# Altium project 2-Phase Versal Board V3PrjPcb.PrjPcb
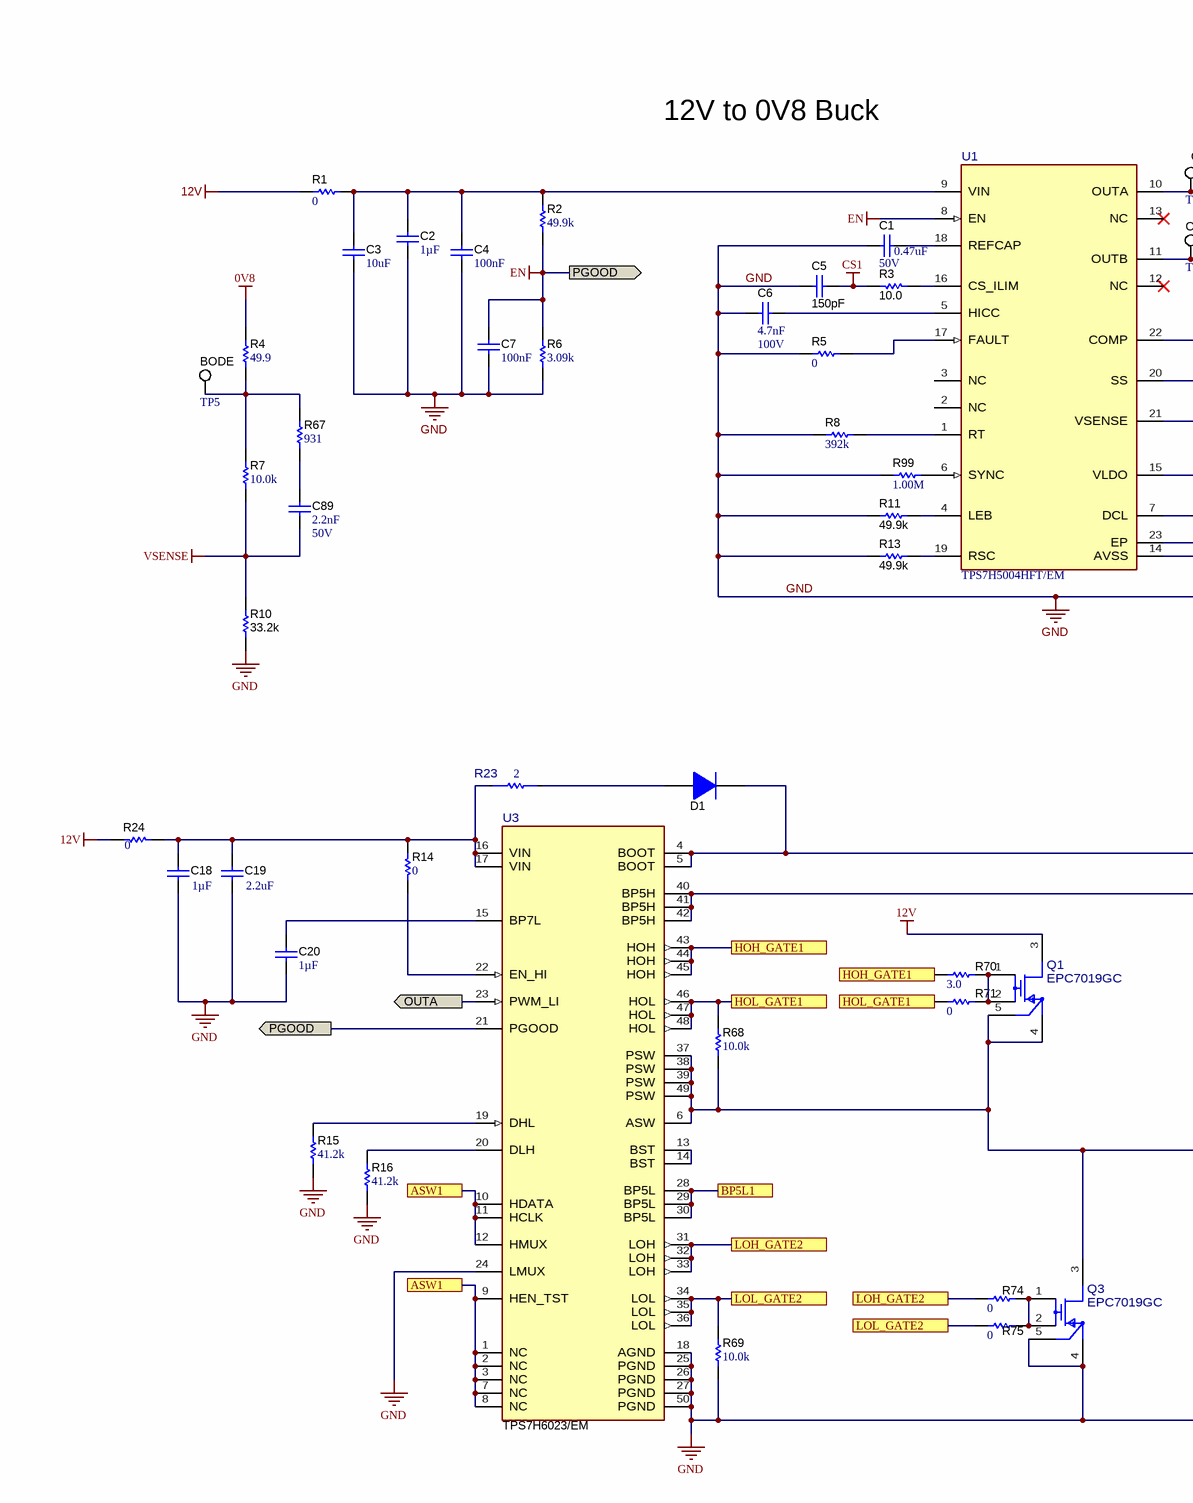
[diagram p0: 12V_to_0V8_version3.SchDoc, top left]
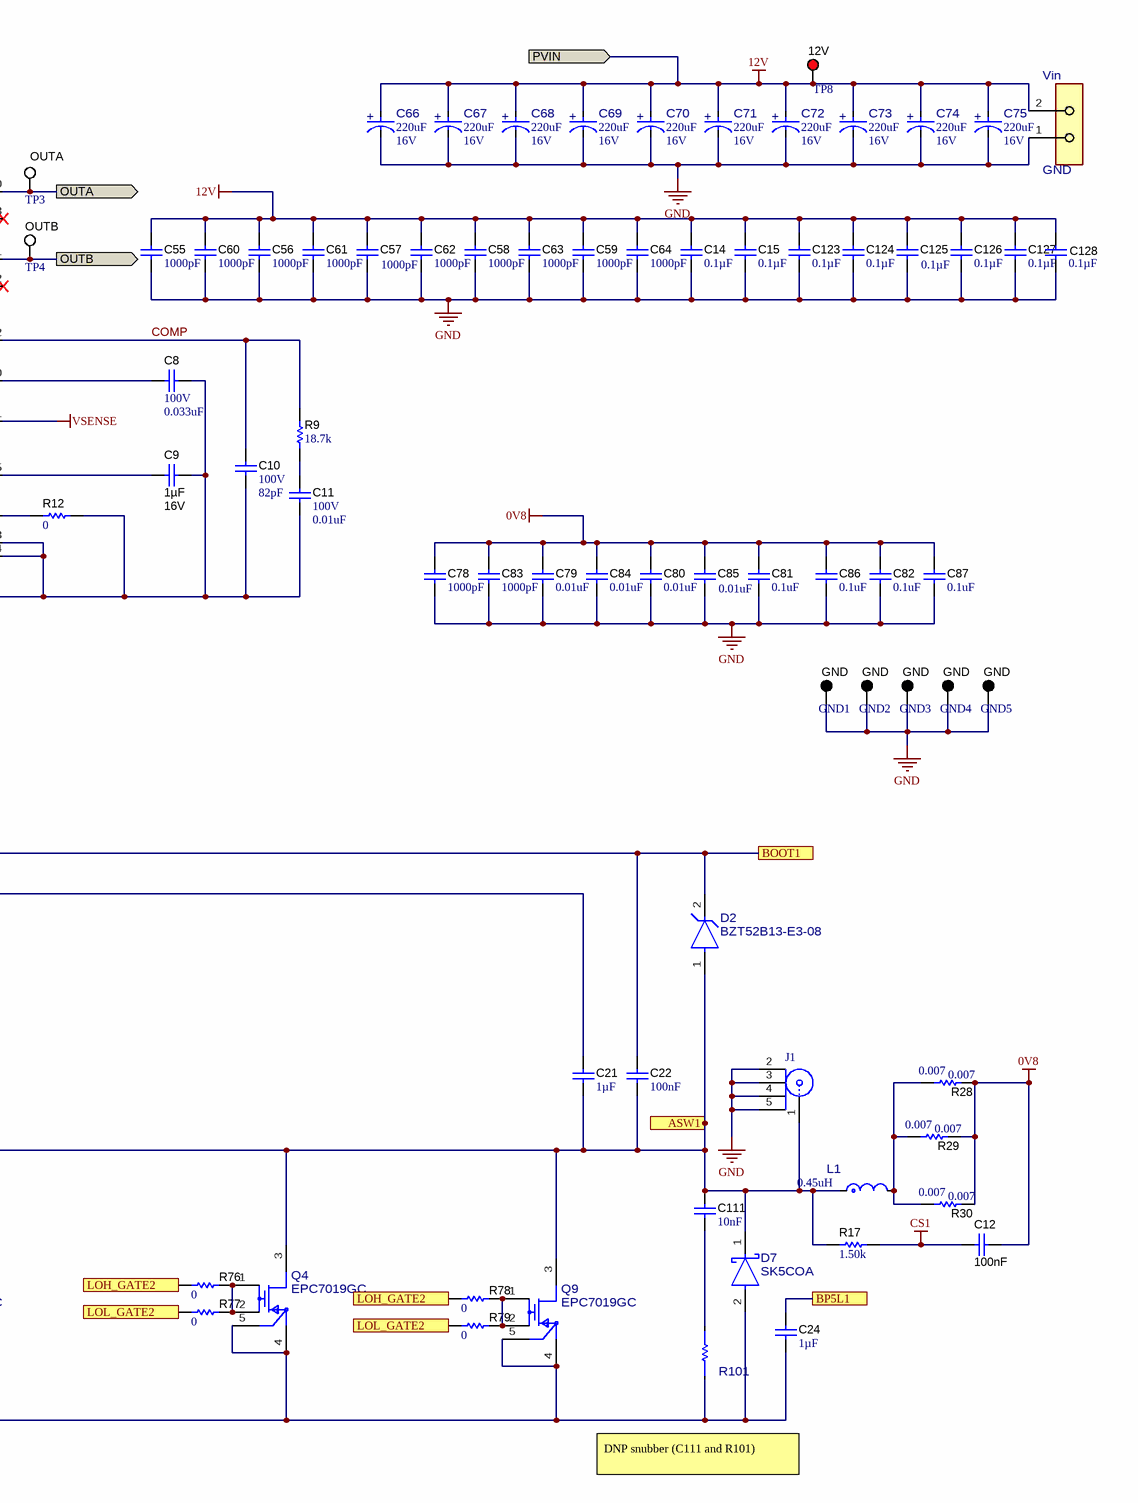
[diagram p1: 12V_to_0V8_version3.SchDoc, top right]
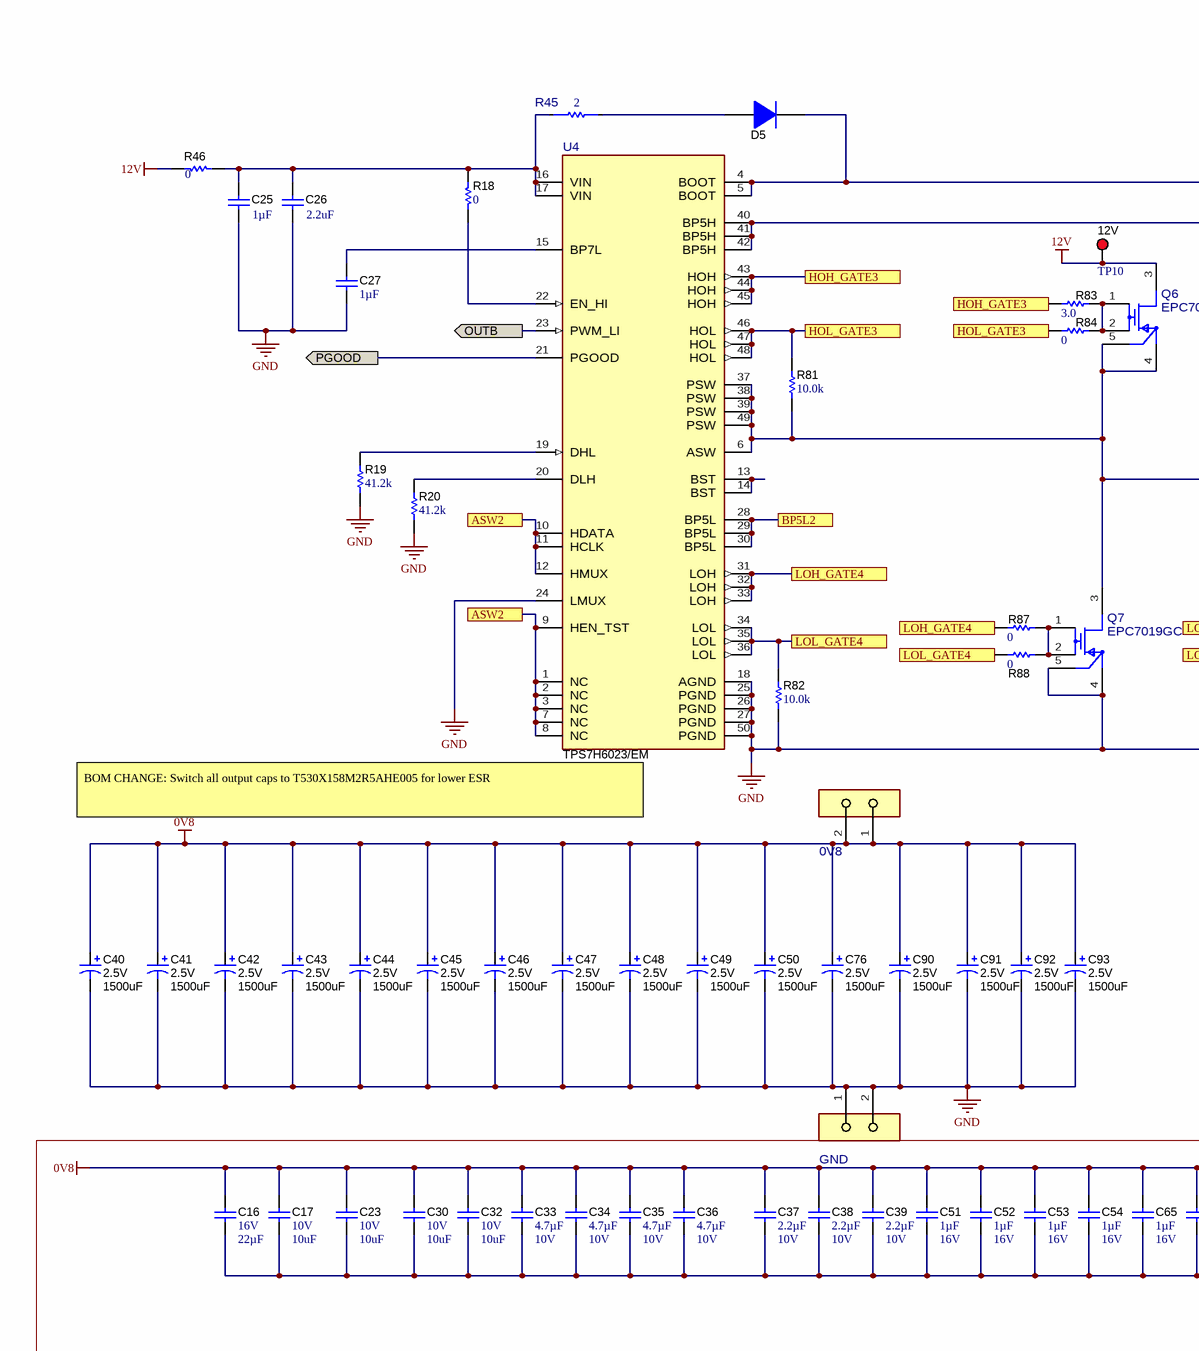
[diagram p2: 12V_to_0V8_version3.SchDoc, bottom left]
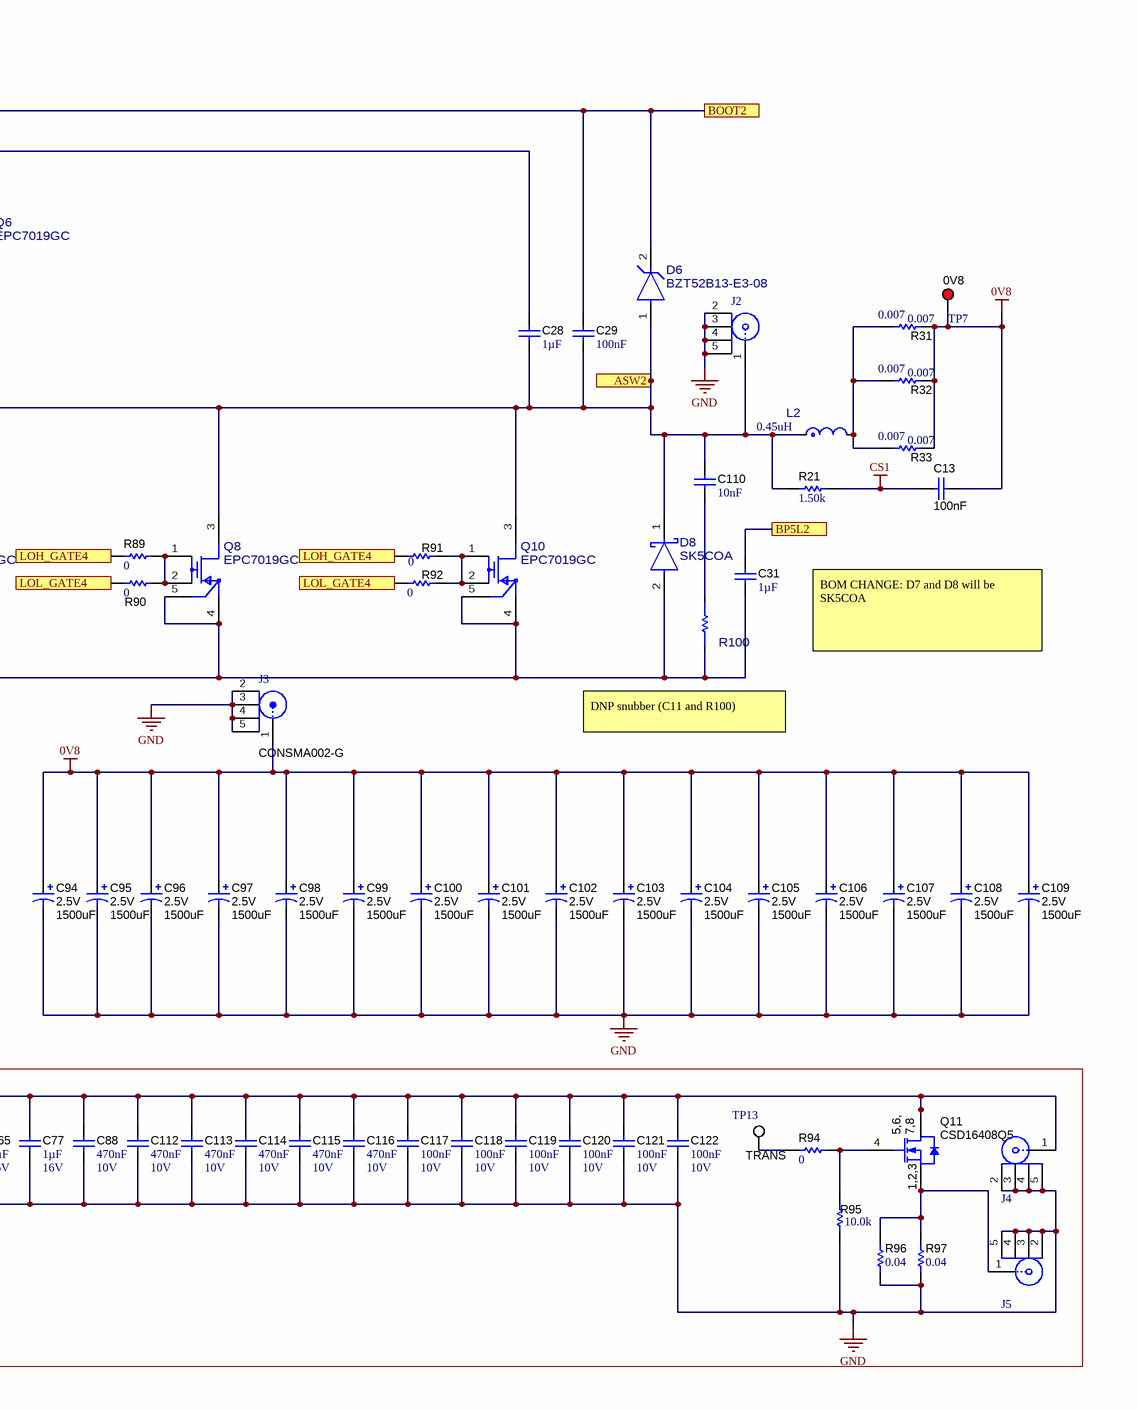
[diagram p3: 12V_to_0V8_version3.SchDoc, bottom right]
CopyrightYear: 2018; PCB_Layout: Who did the Layout?; PCB_Rev: E1; PRJ_Customer: Public Release; PRJ_Engineer: Enter name of project lead; PRJ_Number: XXX###; PRJ_Title: Change in menu Project|Project Options|Parameters; SCH_Rev: E1; TechSupport: http://www.ti.com/support; TID: N/A
2 sheets, 244 parts. Net scope: flat (ports and power ports of the same name join across sheets).
Board file: Versal_V3.PcbDoc
Sheets:
  12V_to_0V8_version3.SchDoc
  Hardware.SchDoc

## Sheet 12V_to_0V8_version3.SchDoc
size 431 x 558 mm; Date: Not shown in title block; ApprovedBy: Not shown in title block; CheckedBy: Not shown in title block; Author: Not shown in title block; CompanyName: Not shown in title block; Engineer: Not shown in title block; Organization: Not shown in title block; Address1: Not shown in title block; Address2: Not shown in title block; Address3: Not shown in title block; Address4: Not shown in title block; DocumentNumber: 1; Revision: Use project parameter SCH_Rev; SheetNumber: 1; SheetTotal: 2; PageSetup: Record=PageOptions¦CenterHorizontal=True¦CenterVertical=True¦PrintScale=1.00¦XCorrection=1.00¦YCorrection=1.00¦PrintKind=0¦BorderSize=5000000¦LeftOffset=0¦BottomOffset=0¦Orientation=2¦PaperLength=1000¦PaperWidth=1000¦Scale=100¦PaperSource=15¦PrintQuality=600¦MediaType=1¦DitherType=10¦PaperKind=Letter¦PrintScaleMode=1

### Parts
0V8  1929517  [FP-1929517_HDR2-MFG]  (value not drawn)
C1  VDC_V: 50V  ValueDisplayed: 0.47uF  [0805L]  (hidden comment: C2012X5R1H474K125AB)
C2  Cap_F: 1µF  [0603L]  (hidden comment: CGA3E1X7R1C105K080AC)
C3  ValueDisplayed: 10uF  [1210_270L]  (hidden comment: GRM32ER71H106KA12L)
C4  Cap_F: 100nF  [0603L]  (hidden comment: C0603C104K5RACAUTO)
C5  Cap_F: 150pF  [0603L]  (hidden comment: 06033C101KAT2A)
C6  Cap_F: 4.7nF  VDC_V: 100V  [0603L]  (hidden comment: GCM188R72A472KA37D)
C7  Cap_F: 100nF  [0603L]  (hidden comment: C0603C104K5RACAUTO)
C8  VDC_V: 100V  ValueDisplayed: 0.033uF  [0603L]  (hidden comment: CGA3E3X7S2A333K080AB)
C9  Cap_F: 1µF  VDC_V: 16V  [0603L]  (hidden comment: CGA3E1X7R1C105K080AC)
C10  VDC_V: 100V  ValueDisplayed: 82pF  [0603]  (hidden comment: GRM1885C2A820JA01D)
C11  VDC_V: 100V  ValueDisplayed: 0.01uF  [0603]  (hidden comment: CGA3E2X7R2A103K080AA)
C12  Cap_F: 100nF  [0603L]  (hidden comment: 06035C104KAZ2A)
C13  Cap_F: 100nF  [0603L]  (hidden comment: 06035C104KAZ2A)
C14  ValueDisplayed: 0.1µF  [0603]  (hidden comment: GCM188R71E104KA57D)
C15  ValueDisplayed: 0.1µF  [0603]  (hidden comment: GCM188R71E104KA57D)
C16  VDC_V: 16V  ValueDisplayed: 22µF  [1210_270]  (hidden comment: CL32B226KOJNFNE)
C17  VDC_V: 10V  ValueDisplayed: 10uF  [1206]  (hidden comment: C3216X7R1A106K085AC)
C18  ValueDisplayed: 1µF  [0805L]  (hidden comment: 08055C105K4Z2A)
C19  ValueDisplayed: 2.2uF  [0805L]  (hidden comment: CGA4J3X7R1H225K125AB)
C20  Cap_F: 1µF  [0805_HV]  (hidden comment: 08055C105K4Z2A)
C21  Cap_F: 1µF  [0805L]  (hidden comment: 08055C105K4Z2A)
C22  Cap_F: 100nF  [0603L]  (hidden comment: C0603C104K5RACAUTO)
C23  VDC_V: 10V  ValueDisplayed: 10uF  [1206]  (hidden comment: C3216X7R1A106K085AC)
C24  Cap_F: 1µF  [0805L]  (hidden comment: 08055C105K4Z2A)
C25  ValueDisplayed: 1µF  [0805L]  (hidden comment: 08055C105K4Z2A)
C26  ValueDisplayed: 2.2uF  [0805L]  (hidden comment: CGA4J3X7R1H225K125AB)
C27  Cap_F: 1µF  [0805_HV]  (hidden comment: 08055C105K4Z2A)
C28  Cap_F: 1µF  [0805L]  (hidden comment: 08055C105K4Z2A)
C29  Cap_F: 100nF  [0603L]  (hidden comment: C0603C104K5RACAUTO)
C30  VDC_V: 10V  ValueDisplayed: 10uF  [1206]  (hidden comment: C3216X7R1A106K085AC)
C31  Cap_F: 1µF  [0805L]  (hidden comment: 08055C105K4Z2A)
C32  VDC_V: 10V  ValueDisplayed: 10uF  [1206]  (hidden comment: C3216X7R1A106K085AC)
C33  Cap_F: 4.7µF  VDC_V: 10V  [0805_HV]  (hidden comment: 885012207025)
C34  Cap_F: 4.7µF  VDC_V: 10V  [0805_HV]  (hidden comment: 885012207025)
C35  Cap_F: 4.7µF  VDC_V: 10V  [0805_HV]  (hidden comment: 885012207025)
C36  Cap_F: 4.7µF  VDC_V: 10V  [0805_HV]  (hidden comment: 885012207025)
C37  Cap_F: 2.2µF  VDC_V: 10V  [0805_HV]  (hidden comment: GRM21BR71A225KA01L)
C38  Cap_F: 2.2µF  VDC_V: 10V  [0805_HV]  (hidden comment: GRM21BR71A225KA01L)
C39  Cap_F: 2.2µF  VDC_V: 10V  [0805_HV]  (hidden comment: GRM21BR71A225KA01L)
C40  VDC_V: 2.5V  ValueDisplayed: 1500uF  [7343-40]  (hidden comment: 2R5TPE1500MF)
C41  VDC_V: 2.5V  ValueDisplayed: 1500uF  [7343-40]  (hidden comment: 2R5TPE1500MF)
C42  VDC_V: 2.5V  ValueDisplayed: 1500uF  [7343-40]  (hidden comment: 2R5TPE1500MF)
C43  VDC_V: 2.5V  ValueDisplayed: 1500uF  [7343-40]  (hidden comment: 2R5TPE1500MF)
C44  VDC_V: 2.5V  ValueDisplayed: 1500uF  [7343-40]  (hidden comment: 2R5TPE1500MF)
C45  VDC_V: 2.5V  ValueDisplayed: 1500uF  [7343-40]  (hidden comment: 2R5TPE1500MF)
C46  VDC_V: 2.5V  ValueDisplayed: 1500uF  [7343-40]  (hidden comment: 2R5TPE1500MF)
C47  VDC_V: 2.5V  ValueDisplayed: 1500uF  [7343-40]  (hidden comment: 2R5TPE1500MF)
C48  VDC_V: 2.5V  ValueDisplayed: 1500uF  [7343-40]  (hidden comment: 2R5TPE1500MF)
C49  VDC_V: 2.5V  ValueDisplayed: 1500uF  [7343-40]  (hidden comment: 2R5TPE1500MF)
C50  VDC_V: 2.5V  ValueDisplayed: 1500uF  [7343-40]  (hidden comment: 2R5TPE1500MF)
C51  Cap_F: 1µF  VDC_V: 16V  [0805_HV]  (hidden comment: C0805C105K4RACAUTO)
C52  Cap_F: 1µF  VDC_V: 16V  [0805_HV]  (hidden comment: C0805C105K4RACAUTO)
C53  Cap_F: 1µF  VDC_V: 16V  [0805_HV]  (hidden comment: C0805C105K4RACAUTO)
C54  Cap_F: 1µF  VDC_V: 16V  [0805_HV]  (hidden comment: C0805C105K4RACAUTO)
C55  ValueDisplayed: 1000pF  [0603]  (hidden comment: 06031C102KAT2A)
C56  ValueDisplayed: 1000pF  [1206]  (hidden comment: 12061C102KAT2A)
C57  ValueDisplayed: 1000pF  [0603]  (hidden comment: 06031C102KAT2A)
C58  ValueDisplayed: 1000pF  [0603]  (hidden comment: 06031C102KAT2A)
C59  ValueDisplayed: 1000pF  [1206]  (hidden comment: 12061C102KAT2A)
C60  ValueDisplayed: 1000pF  [1206]  (hidden comment: 12061C102KAT2A)
C61  ValueDisplayed: 1000pF  [0603]  (hidden comment: 06031C102KAT2A)
C62  ValueDisplayed: 1000pF  [0603]  (hidden comment: 06031C102KAT2A)
C63  ValueDisplayed: 1000pF  [0603]  (hidden comment: 06031C102KAT2A)
C64  ValueDisplayed: 1000pF  [1206]  (hidden comment: 12061C102KAT2A)
C65  Cap_F: 1µF  VDC_V: 16V  [0805_HV]  (hidden comment: C0805C105K4RACAUTO)
C66  ValueDisplayed: 220uF  VDC_V: 16V  [FP-T541X227M016AH6710_2917-MFG]  (hidden comment: T541X227M016AH6710)
C67  ValueDisplayed: 220uF  VDC_V: 16V  [FP-T541X227M016AH6710_2917-MFG]  (hidden comment: T541X227M016AH6710)
C68  ValueDisplayed: 220uF  VDC_V: 16V  [FP-T541X227M016AH6710_2917-MFG]  (hidden comment: T541X227M016AH6710)
C69  ValueDisplayed: 220uF  VDC_V: 16V  [FP-T541X227M016AH6710_2917-MFG]  (hidden comment: T541X227M016AH6710)
C70  ValueDisplayed: 220uF  VDC_V: 16V  [FP-T541X227M016AH6710_2917-MFG]  (hidden comment: T541X227M016AH6710)
C71  ValueDisplayed: 220uF  VDC_V: 16V  [FP-T541X227M016AH6710_2917-MFG]  (hidden comment: T541X227M016AH6710)
C72  ValueDisplayed: 220uF  VDC_V: 16V  [FP-T541X227M016AH6710_2917-MFG]  (hidden comment: T541X227M016AH6710)
C73  ValueDisplayed: 220uF  VDC_V: 16V  [FP-T541X227M016AH6710_2917-MFG]  (hidden comment: T541X227M016AH6710)
C74  ValueDisplayed: 220uF  VDC_V: 16V  [FP-T541X227M016AH6710_2917-MFG]  (hidden comment: T541X227M016AH6710)
C75  ValueDisplayed: 220uF  VDC_V: 16V  [FP-T541X227M016AH6710_2917-MFG]  (hidden comment: T541X227M016AH6710)
C76  VDC_V: 2.5V  ValueDisplayed: 1500uF  [7343-40]  (hidden comment: 2R5TPE1500MF)
C77  Cap_F: 1µF  VDC_V: 16V  [0805_HV]  (hidden comment: C0805C105K4RACAUTO)
C78  ValueDisplayed: 1000pF  [1206L]  (hidden comment: 12061C102KAT2A)
C79  ValueDisplayed: 0.01uF  [1206L]  (hidden comment: C1206C103KARACTU)
C80  ValueDisplayed: 0.01uF  [1206L]  (hidden comment: C1206C103KARACTU)
C81  ValueDisplayed: 0.1uF  [1206_180]  (hidden comment: GRM31CR72E104KW03L)
C82  ValueDisplayed: 0.1uF  [1206_180]  (hidden comment: GRM31CR72E104KW03L)
C83  ValueDisplayed: 1000pF  [1206L]  (hidden comment: 12061C102KAT2A)
C84  ValueDisplayed: 0.01uF  [1206L]  (hidden comment: C1206C103KARACTU)
C85  ValueDisplayed: 0.01uF  [1206L]  (hidden comment: C1206C103KARACTU)
C86  ValueDisplayed: 0.1uF  [1206_180]  (hidden comment: GRM31CR72E104KW03L)
C87  ValueDisplayed: 0.1uF  [1206_180]  (hidden comment: GRM31CR72E104KW03L)
C88  Cap_F: 470nF  VDC_V: 10V  [0603]  (hidden comment: C0603C474K8RACTU)
C89  Cap_F: 2.2nF  VDC_V: 50V  [0805_HV]  (hidden comment: 08055A222JAT2A)
C90  VDC_V: 2.5V  ValueDisplayed: 1500uF  [7343-40]  (hidden comment: 2R5TPE1500MF)
C91  VDC_V: 2.5V  ValueDisplayed: 1500uF  [7343-40]  (hidden comment: 2R5TPE1500MF)
C92  VDC_V: 2.5V  ValueDisplayed: 1500uF  [7343-40]  (hidden comment: 2R5TPE1500MF)
C93  VDC_V: 2.5V  ValueDisplayed: 1500uF  [7343-40]  (hidden comment: 2R5TPE1500MF)
C94  VDC_V: 2.5V  ValueDisplayed: 1500uF  [7343-40]  (hidden comment: 2R5TPE1500MF)
C95  VDC_V: 2.5V  ValueDisplayed: 1500uF  [7343-40]  (hidden comment: 2R5TPE1500MF)
C96  VDC_V: 2.5V  ValueDisplayed: 1500uF  [7343-40]  (hidden comment: 2R5TPE1500MF)
C97  VDC_V: 2.5V  ValueDisplayed: 1500uF  [7343-40]  (hidden comment: 2R5TPE1500MF)
C98  VDC_V: 2.5V  ValueDisplayed: 1500uF  [7343-40]  (hidden comment: 2R5TPE1500MF)
C99  VDC_V: 2.5V  ValueDisplayed: 1500uF  [7343-40]  (hidden comment: 2R5TPE1500MF)
C100  VDC_V: 2.5V  ValueDisplayed: 1500uF  [7343-40]  (hidden comment: 2R5TPE1500MF)
C101  VDC_V: 2.5V  ValueDisplayed: 1500uF  [7343-40]  (hidden comment: 2R5TPE1500MF)
C102  VDC_V: 2.5V  ValueDisplayed: 1500uF  [7343-40]  (hidden comment: 2R5TPE1500MF)
C103  VDC_V: 2.5V  ValueDisplayed: 1500uF  [7343-40]  (hidden comment: 2R5TPE1500MF)
C104  VDC_V: 2.5V  ValueDisplayed: 1500uF  [7343-40]  (hidden comment: 2R5TPE1500MF)
C105  VDC_V: 2.5V  ValueDisplayed: 1500uF  [7343-40]  (hidden comment: 2R5TPE1500MF)
C106  VDC_V: 2.5V  ValueDisplayed: 1500uF  [7343-40]  (hidden comment: 2R5TPE1500MF)
C107  VDC_V: 2.5V  ValueDisplayed: 1500uF  [7343-40]  (hidden comment: 2R5TPE1500MF)
C108  VDC_V: 2.5V  ValueDisplayed: 1500uF  [7343-40]  (hidden comment: 2R5TPE1500MF)
C109  VDC_V: 2.5V  ValueDisplayed: 1500uF  [7343-40]  (hidden comment: 2R5TPE1500MF)
C110  Cap_F: 10nF  [0603]  (hidden comment: 0603ZC103KAT2A)
C111  Cap_F: 10nF  [0603]  (hidden comment: 0603ZC103KAT2A)
C112  Cap_F: 470nF  VDC_V: 10V  [0603]  (hidden comment: C0603C474K8RACTU)
C113  Cap_F: 470nF  VDC_V: 10V  [0603]  (hidden comment: C0603C474K8RACTU)
C114  Cap_F: 470nF  VDC_V: 10V  [0603]  (hidden comment: C0603C474K8RACTU)
C115  Cap_F: 470nF  VDC_V: 10V  [0603]  (hidden comment: C0603C474K8RACTU)
C116  Cap_F: 470nF  VDC_V: 10V  [0603]  (hidden comment: C0603C474K8RACTU)
C117  Cap_F: 100nF  VDC_V: 10V  [0603]  (hidden comment: 885012206020)
C118  Cap_F: 100nF  VDC_V: 10V  [0603]  (hidden comment: 885012206020)
C119  Cap_F: 100nF  VDC_V: 10V  [0603]  (hidden comment: 885012206020)
C120  Cap_F: 100nF  VDC_V: 10V  [0603]  (hidden comment: 885012206020)
C121  Cap_F: 100nF  VDC_V: 10V  [0603]  (hidden comment: 885012206020)
C122  Cap_F: 100nF  VDC_V: 10V  [0603]  (hidden comment: 885012206020)
C123  ValueDisplayed: 0.1µF  [0603]  (hidden comment: GCM188R71E104KA57D)
C124  ValueDisplayed: 0.1µF  [0603]  (hidden comment: GCM188R71E104KA57D)
C125  ValueDisplayed: 0.1µF  [0603]  (hidden comment: GCM188R71E104KA57D)
C126  ValueDisplayed: 0.1µF  [0603]  (hidden comment: GCM188R71E104KA57D)
C127  ValueDisplayed: 0.1µF  [0603]  (hidden comment: GCM188R71E104KA57D)
C128  ValueDisplayed: 0.1µF  [0603]  (hidden comment: GCM188R71E104KA57D)
D1  ES3AB-13-F  [SMB]  (value not drawn)
D2  BZT52B13-E3-08  [FP-BZT52B13-E3-08_SOD123-MFG]
D5  ES3AB-13-F  [SMB]  (value not drawn)
D6  BZT52B13-E3-08  [FP-BZT52B13-E3-08_SOD123-MFG]
D7  SK5COA  [FP-NRVBA340T3G_SMA-MFG]
D8  SK5COA  [FP-NRVBA340T3G_SMA-MFG]
GND  1929517  [FP-1929517_HDR2-MFG]  (value not drawn)
GND1  GND  [Keystone5001]
GND2  GND  [Keystone5001]
GND3  GND  [Keystone5001]
GND4  GND  [Keystone5001]
GND5  GND  [Keystone5001]
J1  SW  [Tek_131-5031-00]  (value not drawn)
J2  SW  [Tek_131-5031-00]  (value not drawn)
J3  CONSMA002-G  [Linx_CONSMA002-G]
J4  SW  [Tek_131-5031-00]  (value not drawn)
J5  SW  [Tek_131-5031-00]  (value not drawn)
L1  value 0.45uH  [FP-XAL1010-451MEB_SMD2-MFG]  (hidden comment: XAL1010-451MEB)
L2  value 0.45uH  [FP-XAL1010-451MEB_SMD2-MFG]  (hidden comment: XAL1010-451MEB)
Q1  EPC7019GC  [FP-EPC7019GC_FSMD-G-MFG]
Q3  EPC7019GC  [FP-EPC7019GC_FSMD-G-MFG]
Q4  EPC7019GC  [FP-EPC7019GC_FSMD-G-MFG]
Q6  EPC7019GC  [FP-EPC7019GC_FSMD-G-MFG]
Q7  EPC7019GC  [FP-EPC7019GC_FSMD-G-MFG]
Q8  EPC7019GC  [FP-EPC7019GC_FSMD-G-MFG]
Q9  EPC7019GC  [FP-EPC7019GC_FSMD-G-MFG]
Q10  EPC7019GC  [FP-EPC7019GC_FSMD-G-MFG]
Q11  CSD16408Q5  [DQH0008A]
R1  ValueDisplayed: 0  [0603L]  (hidden comment: RMCF0603ZT0R00)
R2  ValueDisplayed: 49.9k  [0603L]  (hidden comment: RC0603FR-0749K9L)
R3  ValueDisplayed: 10.0  [0603L]  (hidden comment: RC0603FR-0710RL)
R4  ValueDisplayed: 49.9  [0603L]  (hidden comment: RC0603FR-0749R9L)
R5  ValueDisplayed: 0  [0603L]  (hidden comment: RMCF0603ZT0R00)
R6  ValueDisplayed: 3.09k  [0603L]  (hidden comment: RC0603FR-073K09L)
R7  ValueDisplayed: 10.0k  [0603L]  (hidden comment: RG1608P-103-B-T5)
R8  ValueDisplayed: 392k  [0603L]  (hidden comment: RC0603FR-07392KL)
R9  ValueDisplayed: 18.7k  [0603]  (hidden comment: CRCW060318K7FKEA)
R10  ValueDisplayed: 33.2k  [0603L]  (hidden comment: RG1608P-3322-B-T5)
R11  ValueDisplayed: 49.9k  [0603L]  (hidden comment: RT0603DRE0749K9L)
R12  ValueDisplayed: 0  [0603L]  (hidden comment: RMCF0603ZT0R00)
R13  ValueDisplayed: 49.9k  [0603L]  (hidden comment: RT0603DRE0749K9L)
R14  ValueDisplayed: 0  [0603L]  (hidden comment: RMCF0603ZT0R00)
R15  ValueDisplayed: 41.2k  [0805L]  (hidden comment: RT0805BRD0741K2L)
R16  ValueDisplayed: 41.2k  [0805L]  (hidden comment: RT0805BRD0741K2L)
R17  ValueDisplayed: 1.50k  [0603]  (hidden comment: RT0603BRD071K5L)
R18  ValueDisplayed: 0  [0603L]  (hidden comment: RMCF0603ZT0R00)
R19  ValueDisplayed: 41.2k  [0805L]  (hidden comment: RT0805BRD0741K2L)
R20  ValueDisplayed: 41.2k  [0805L]  (hidden comment: RT0805BRD0741K2L)
R21  ValueDisplayed: 1.50k  [0603]  (hidden comment: RT0603BRD071K5L)
R23  value 2  [FP-RCS06032R00FKEA_0603-MFG]  (hidden comment: RCS06032R00FKEA)
R24  ValueDisplayed: 0  [0603L]  (hidden comment: RMCF0603ZT0R00)
R28  value 0.007  [2512_WIDE]  (hidden comment: KRL6432E-M-R007-F-T1)
R29  value 0.007  [2512_WIDE]  (hidden comment: KRL6432E-M-R007-F-T1)
R30  value 0.007  [2512_WIDE]  (hidden comment: KRL6432E-M-R007-F-T1)
R31  value 0.007  [2512_WIDE]  (hidden comment: KRL6432E-M-R007-F-T1)
R32  value 0.007  [2512_WIDE]  (hidden comment: KRL6432E-M-R007-F-T1)
R33  value 0.007  [2512_WIDE]  (hidden comment: KRL6432E-M-R007-F-T1)
R45  value 2  [FP-RCS06032R00FKEA_0603-MFG]  (hidden comment: RCS06032R00FKEA)
R46  ValueDisplayed: 0  [0603L]  (hidden comment: RMCF0603ZT0R00)
R67  ValueDisplayed: 931  [0603]  (hidden comment: RT0603BRD07931RL)
R68  ValueDisplayed: 10.0k  [0603L]  (hidden comment: RCG060310K0FKEA)
R69  ValueDisplayed: 10.0k  [0603L]  (hidden comment: RCG060310K0FKEA)
R70  ValueDisplayed: 3.0  [0603]  (hidden comment: CRCW06033R00JNEA)
R71  ValueDisplayed: 0  [0603L]  (hidden comment: RMCF0603ZT0R00)
R74  ValueDisplayed: 0  [0603L]  (hidden comment: RMCF0603ZT0R00)
R75  ValueDisplayed: 0  [0603L]  (hidden comment: RMCF0603ZT0R00)
R76  ValueDisplayed: 0  [0603L]  (hidden comment: RMCF0603ZT0R00)
R77  ValueDisplayed: 0  [0603L]  (hidden comment: RMCF0603ZT0R00)
R78  ValueDisplayed: 0  [0603L]  (hidden comment: RMCF0603ZT0R00)
R79  ValueDisplayed: 0  [0603L]  (hidden comment: RMCF0603ZT0R00)
R81  ValueDisplayed: 10.0k  [0603L]  (hidden comment: RCG060310K0FKEA)
R82  ValueDisplayed: 10.0k  [0603L]  (hidden comment: RCG060310K0FKEA)
R83  ValueDisplayed: 3.0  [0603]  (hidden comment: CRCW06033R00JNEA)
R84  ValueDisplayed: 0  [0603L]  (hidden comment: RMCF0603ZT0R00)
R87  ValueDisplayed: 0  [0603L]  (hidden comment: RMCF0603ZT0R00)
R88  ValueDisplayed: 0  [0603L]  (hidden comment: RMCF0603ZT0R00)
R89  ValueDisplayed: 0  [0603L]  (hidden comment: RMCF0603ZT0R00)
R90  ValueDisplayed: 0  [0603L]  (hidden comment: RMCF0603ZT0R00)
R91  ValueDisplayed: 0  [0603L]  (hidden comment: RMCF0603ZT0R00)
R92  ValueDisplayed: 0  [0603L]  (hidden comment: RMCF0603ZT0R00)
R94  ValueDisplayed: 0  [0603L]  (hidden comment: RCS06030000Z0EA)
R95  ValueDisplayed: 10.0k  [0603L]  (hidden comment: PHT0603Y1002BGT200)
R96  ValueDisplayed: 0.04  [2512]  (hidden comment: WSL2512R0400FEA18)
R97  ValueDisplayed: 0.04  [2512]  (hidden comment: WSL2512R0400FEA18)
R99  ValueDisplayed: 1.00M  [0603L]  (hidden comment: RC0603FR-071ML)
R100  VMS-R500-1.0-U  [FP-VMS-R500-1.0-U_2512-MFG]  (value not drawn)
R101  VMS-R500-1.0-U  [FP-VMS-R500-1.0-U_2512-MFG]  (value not drawn)
TP3  OUTA  [Keystone5002]
TP4  OUTB  [Keystone5002]
TP5  BODE  [Keystone5002]
TP7  0V8  [Keystone5000]
TP8  12V  [Keystone5000]
TP10  12V  [Keystone5000]
TP13  TRANS  [Testpoint_Keystone_Miniature]
U1  TPS7H5004HFT/EM  [HFT0022A-C01-MFG]
U3  TPS7H6023/EM  [HBX0048A-IPC_C]
U4  TPS7H6023/EM  [HBX0048A-IPC_C]
Vin  GND  [FP-1929517_HDR2-MFG]

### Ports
ASW1, ASW2, BOOT1, BOOT2, BP5L1, BP5L2, HOH_GATE1, HOH_GATE3, HOL_GATE1, HOL_GATE3, LOH_GATE2, LOH_GATE4, LOL_GATE2, LOL_GATE4, OUTA (out), OUTB (out), PGOOD (out), PVIN (in)

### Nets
0V8: 0V8.1 0V8.2 C12.1 C13.1 C16.1 C17.1 C23.1 C30.1 C32.1 C33.1 C34.1 C35.1 C36.1 C37.1 C38.1 C39.1 C40.1(+) C41.1(+) C42.1(+) C43.1(+) C44.1(+) C45.1(+) C46.1(+) C47.1(+) C48.1(+) C49.1(+) C50.1(+) C51.1 C52.1 C53.1 C54.1 C65.1 C76.1(+) C77.1 C78.1 C79.1 C80.1 C81.1 C82.1 C83.1 C84.1 C85.1 C86.1 C87.1 C88.1 C90.1(+) C91.1(+) C92.1(+) C93.1(+) C94.1(+) C95.1(+) C96.1(+) C97.1(+) C98.1(+) C99.1(+) C100.1(+) C101.1(+) C102.1(+) C103.1(+) C104.1(+) C105.1(+) C106.1(+) C107.1(+) C108.1(+) C109.1(+) C112.1 C113.1 C114.1 C115.1 C116.1 C117.1 C118.1 C119.1 C120.1 C121.1 C122.1 J3.1 J4.1 Q11.5(D) Q11.6(D) Q11.7(D) Q11.8(D) Q11.9(D) R4.2 R28.2 R29.2 R30.2 R31.2 R32.2 R33.2 TP7.1
12V: C14.1 C15.1 C55.1 C56.1 C57.1 C58.1 C59.1 C60.1 C61.1 C62.1 C63.1 C64.1 C66.2(ANODE) C67.2(ANODE) C68.2(ANODE) C69.2(ANODE) C70.2(ANODE) C71.2(ANODE) C72.2(ANODE) C73.2(ANODE) C74.2(ANODE) C75.2(ANODE) C123.1 C124.1 C125.1 C126.1 C127.1 C128.1 Q1.3(D) Q6.3(D) R1.1 R24.2 R46.2 TP8.1 TP10.1 Vin.2 ; port PVIN
CS1: C5.2 C12.2 C13.2 R3.2 R17.2 R21.2
EN: C7.1 R2.1 R6.2 U1.8(EN) U3.21(PGOOD) U4.21(PGOOD) ; port PGOOD
GND: C1.2 C2.2 C3.2 C4.2 C5.1 C6.2 C7.2 C8.1 C9.1 C10.2 C11.2 C14.2 C15.2 C16.2 C17.2 C18.2 C19.2 C20.2 C23.2 C24.2 C25.2 C26.2 C27.2 C30.2 C31.2 C32.2 C33.2 C34.2 C35.2 C36.2 C37.2 C38.2 C39.2 C40.2(-) C41.2(-) C42.2(-) C43.2(-) C44.2(-) C45.2(-) C46.2(-) C47.2(-) C48.2(-) C49.2(-) C50.2(-) C51.2 C52.2 C53.2 C54.2 C55.2 C56.2 C57.2 C58.2 C59.2 C60.2 C61.2 C62.2 C63.2 C64.2 C65.2 C66.1(CATHODE) C67.1(CATHODE) C68.1(CATHODE) C69.1(CATHODE) C70.1(CATHODE) C71.1(CATHODE) C72.1(CATHODE) C73.1(CATHODE) C74.1(CATHODE) C75.1(CATHODE) C76.2(-) C77.2 C78.2 C79.2 C80.2 C81.2 C82.2 C83.2 C84.2 C85.2 C86.2 C87.2 C88.2 C90.2(-) C91.2(-) C92.2(-) C93.2(-) C94.2(-) C95.2(-) C96.2(-) C97.2(-) C98.2(-) C99.2(-) C100.2(-) C101.2(-) C102.2(-) C103.2(-) C104.2(-) C105.2(-) C106.2(-) C107.2(-) C108.2(-) C109.2(-) C112.2 C113.2 C114.2 C115.2 C116.2 C117.2 C118.2 C119.2 C120.2 C121.2 C122.2 C123.2 C124.2 C125.2 C126.2 C127.2 C128.2 D7.2(Anode) D8.2(Anode) GND.1 GND.2 GND1.1 GND2.1 GND3.1 GND4.1 GND5.1 J1.2 J1.3 J1.4 J1.5 J2.2 J2.3 J2.4 J2.5 J3.2 J3.3 J3.4 J3.5 J4.2 J4.3 J4.4 J4.5 J5.2 J5.3 J5.4 J5.5 Q3.4(S) Q3.5(SS) Q4.4(S) Q4.5(SS) Q7.4(S) Q7.5(SS) Q8.4(S) Q8.5(SS) Q9.4(S) Q9.5(SS) Q10.4(S) Q10.5(SS) R5.2 R6.1 R8.2 R10.1 R11.1 R12.1 R13.1 R15.1 R16.1 R19.1 R20.1 R69.1 R82.1 R95.1 R96.1 R97.1 R99.2 R100.1 R101.1 U1.14(AVSS) U1.23(EP) U3.18(AGND) U3.24(LMUX) U3.25(PGND) U3.26(PGND) U3.27(PGND) U3.50(PGND) U4.18(AGND) U4.24(LMUX) U4.25(PGND) U4.26(PGND) U4.27(PGND) U4.50(PGND) Vin.1
VSENSE: C89.2 R7.1 R10.2 U1.21(VSENSE)
ASW1: C21.2 C22.2 C111.1 D2.1(ANODE) D7.1(Cathode) J1.1 L1.1 Q1.4(S) Q1.5(SS) Q3.3(D) Q4.3(D) Q9.3(D) R17.1 R68.1 U3.1(NC) U3.2(NC) U3.3(NC) U3.6(ASW) U3.7(NC) U3.8(NC) U3.9(HEN_TST) U3.10(HDATA) U3.11(HCLK) U3.12(HMUX) U3.37(PSW) U3.38(PSW) U3.39(PSW) U3.49(PSW) ; port ASW1
ASW2: C28.2 C29.2 C110.1 D6.1(ANODE) D8.1(Cathode) J2.1 L2.1 Q6.4(S) Q6.5(SS) Q7.3(D) Q8.3(D) Q10.3(D) R21.1 R81.1 U4.1(NC) U4.2(NC) U4.3(NC) U4.6(ASW) U4.7(NC) U4.8(NC) U4.9(HEN_TST) U4.10(HDATA) U4.11(HCLK) U4.12(HMUX) U4.37(PSW) U4.38(PSW) U4.39(PSW) U4.49(PSW) ; port ASW2
BOOT1: C22.1 D1.1(K) D2.2(CATHODE) U3.4(BOOT) U3.5(BOOT) ; port BOOT1
BOOT2: C29.1 D5.1(K) D6.2(CATHODE) U4.4(BOOT) U4.5(BOOT) ; port BOOT2
BP5L1: C24.1 U3.28(BP5L) U3.29(BP5L) U3.30(BP5L) ; port BP5L1
BP5L2: C31.1 U4.28(BP5L) U4.29(BP5L) U4.30(BP5L) ; port BP5L2
COMP: C10.1 R9.2 U1.22(COMP)
HOH_GATE1: R70.1 U3.43(HOH) U3.44(HOH) U3.45(HOH) ; port HOH_GATE1
HOH_GATE3: R83.1 U4.43(HOH) U4.44(HOH) U4.45(HOH) ; port HOH_GATE3
HOL_GATE1: R68.2 R71.1 U3.46(HOL) U3.47(HOL) U3.48(HOL) ; port HOL_GATE1
HOL_GATE3: R81.2 R84.1 U4.46(HOL) U4.47(HOL) U4.48(HOL) ; port HOL_GATE3
LOH_GATE2: R74.1 R76.1 R78.1 U3.31(LOH) U3.32(LOH) U3.33(LOH) ; port LOH_GATE2
LOH_GATE4: R87.1 R89.1 R91.1 U4.31(LOH) U4.32(LOH) U4.33(LOH) ; port LOH_GATE4
LOL_GATE2: R69.2 R75.1 R77.1 R79.1 U3.34(LOL) U3.35(LOL) U3.36(LOL) ; port LOL_GATE2
LOL_GATE4: R82.2 R88.1 R90.1 R92.1 U4.34(LOL) U4.35(LOL) U4.36(LOL) ; port LOL_GATE4
OUTA: TP3.1 U1.10(OUTA) U3.23(PWM_LI) ; port OUTA
OUTB: TP4.1 U1.11(OUTB) U4.23(PWM_LI) ; port OUTB
NetC1_1: C1.1 U1.18(REFCAP)
NetC2_1: C2.1 C3.1 C4.1 R1.2 R2.2 U1.9(VIN)
NetC6_1: C6.1 U1.5(HICC)
NetC8_2: C8.2 U1.20(SS)
NetC9_2: C9.2 U1.15(VLDO)
NetC11_1: C11.1 R9.1
NetC18_1: C18.1 C19.1 R14.1 R23.1 R24.1 U3.16(VIN) U3.17(VIN)
NetC20_1: C20.1 U3.15(BP7L)
NetC21_1: C21.1 U3.40(BP5H) U3.41(BP5H) U3.42(BP5H)
NetC25_1: C25.1 C26.1 R18.1 R45.1 R46.1 U4.16(VIN) U4.17(VIN)
NetC27_1: C27.1 U4.15(BP7L)
NetC28_1: C28.1 U4.40(BP5H) U4.41(BP5H) U4.42(BP5H)
NetC89_1: C89.1 R67.1
NetC110_2: C110.2 R100.2
NetC111_2: C111.2 R101.2
NetD1_2: D1.2(A) R23.2
NetD5_2: D5.2(A) R45.2
NetJ5_1: J5.1 Q11.1(S) Q11.2(S) Q11.3(S) R96.2 R97.2
NetL1_2: L1.2 R28.1 R29.1 R30.1
NetL2_2: L2.2 R31.1 R32.1 R33.1
NetQ1_1: Q1.1(G) Q1.2(G) R70.2 R71.2
NetQ3_1: Q3.1(G) Q3.2(G) R74.2 R75.2
NetQ4_1: Q4.1(G) Q4.2(G) R76.2 R77.2
NetQ6_1: Q6.1(G) Q6.2(G) R83.2 R84.2
NetQ7_1: Q7.1(G) Q7.2(G) R87.2 R88.2
NetQ8_1: Q8.1(G) Q8.2(G) R89.2 R90.2
NetQ9_1: Q9.1(G) Q9.2(G) R78.2 R79.2
NetQ10_1: Q10.1(G) Q10.2(G) R91.2 R92.2
NetQ11_4: Q11.4(G) R94.2 R95.2
NetR3_1: R3.1 U1.16(CS_ILIM)
NetR4_1: R4.1 R7.2 R67.2 TP5.1
NetR5_1: R5.1 U1.17(FAULT)
NetR8_1: R8.1 U1.1(RT)
NetR11_2: R11.2 U1.4(LEB)
NetR12_2: R12.2 U1.7(DCL)
NetR13_2: R13.2 U1.19(RSC)
NetR14_2: R14.2 U3.22(EN_HI)
NetR15_2: R15.2 U3.19(DHL)
NetR16_2: R16.2 U3.20(DLH)
NetR18_2: R18.2 U4.22(EN_HI)
NetR19_2: R19.2 U4.19(DHL)
NetR20_2: R20.2 U4.20(DLH)
NetR94_1: R94.1 TP13.1
NetR99_1: R99.1 U1.6(SYNC)
NetU3_13: U3.13(BST) U3.14(BST)
NetU4_13: U4.13(BST) U4.14(BST)

Not connected (* = marked no-connect by the designer): U1 2(NC) 3(NC) 12(NC)* 13(NC)*

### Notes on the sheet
- 12V to 0V8 Buck
- DNP snubber (C111 and R101)
- BOM CHANGE: D7 and D8 will be SK5COA
- (near U4) BOM CHANGE: Switch all output caps to T530X158M2R5AHE005 for lower ESR
- (near R100) DNP snubber (C11 and R100)

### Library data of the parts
0V8 GND = CMP-0078537-1: Fixed Terminal Blocks MKDSP 10 HV/ 2-10; Manufacturer: Phoenix Contact; Voltage_V: 1kV; Current_A: 76A; Row_Count: 1
C1 = CMP-0007839-2: CAP, CERM, 0.47 uF, 50 V, +/- 10%, X5R, 0805; Manufacturer: TDK; TaMin_C: -55°C; ESR_ohm: 22.012m; Polarized: N; SizeAreaWB_mm2: 6.75; Value1: 0.022012 ohm; U/M: EA; Value: 0.47uF; TaMax_C: 85°C; SizeZ_mm: 1.45; SizeX_mm: 2; SizeY_mm: 1.25; Cap_Case: 0805; SizeArea_mm2: 2.5; Cap_F: 470nF; IRMS_A: 1.3957A; AEC Category: Q200
C2 = CMP-0079607-1: CAP, CERM, 1 µF, 16 V,+/- 10%, X7R, AEC-Q200 Grade 1, 0603; Manufacturer: TDK; TaMin_C: -55°C; Polarized: N; SizeAreaWB_mm2: 4.68; U/M: EA; Value: 1uF; TaMax_C: 125°C; SizeZ_mm: 1; SizeX_mm: 1.6; SizeY_mm: 0.8; Cap_Case: 0603; Value2: 16V; SizeArea_mm2: 1.28; AEC Qualified: Y; AEC Category: Q200
C3 = CMP-0009226-3: CAP, CERM, 10 uF, 50 V, +/- 10%, X7R, 1210; Manufacturer: MuRata; TaMin_C: -55°C; Polarized: N; SizeAreaWB_mm2: 14.7; Value1: Unknown; U/M: EA; Value: 10uF; TaMax_C: 125°C; SizeZ_mm: 2.7; SizeX_mm: 3.2; SizeY_mm: 2.5; Cap_Case: 1210; Value2: 50V; SizeArea_mm2: 8; Cap_F: 10µF; AEC Category: Q200
C4 C7 C22 C29 = CMP-0079602-1: CAP, CERM, 0.1 µF, 50 V,+/- 10%, X7R, AEC-Q200 Grade 1, 0603; Manufacturer: Kemet; TaMin_C: -55°C; Polarized: N; SizeAreaWB_mm2: 4.68; U/M: EA; Value: 0.1uF; TaMax_C: 125°C; SizeZ_mm: 1; SizeX_mm: 1.6; SizeY_mm: 0.8; Cap_Case: 0603; Value2: 50V; SizeArea_mm2: 1.28; AEC Qualified: Y; AEC Category: Q200; ValueDisplayed: 0.1µF
C5 = CMP-0006751-4: CAP, CERM, 100 pF, 25 V, +/- 10%, X7R, 0603; Manufacturer: AVX; TaMin_C: -55°C; Polarized: N; SizeAreaWB_mm2: 4.68; Value1: Unknown; U/M: EA; Value: 100pF; TaMax_C: 125°C; SizeZ_mm: 1; SizeX_mm: 1.6; SizeY_mm: 0.8; Cap_Case: 0603; Value2: 25V; SizeArea_mm2: 1.28; AEC Category: Q200
C6 = CMP-0079247-1: CAP, CERM, 4700 pF, 100 V,+/- 10%, X7R, AEC-Q200 Grade 1, 0603; Manufacturer: MuRata; SizeAreaWB_mm2: 4.68; SizeArea_mm2: 1.28; AEC Qualified: Y; AEC Category: Q200; Value: 4700pF; TaMax_C: 125°C; SizeZ_mm: 1; Polarized: N; TaMin_C: -55°C; SizeY_mm: 0.8; U/M: EA; SizeX_mm: 1.6; Cap_Case: 0603
C8 = CMP-0007100-4: CAP, CERM, 0.033 uF, 100 V, +/- 10%, X7S, AEC-Q200 Grade 1, 0603; Manufacturer: TDK; TaMin_C: -55°C; ESR_ohm: 0.1396; Polarized: N; SizeAreaWB_mm2: 4.68; Value1: 0.139637 ohm; U/M: EA; TaMax_C: 125°C; SizeZ_mm: 1; SizeX_mm: 1.6; SizeY_mm: 0.8; Cap_Case: 0603; SizeArea_mm2: 1.28; AEC Qualified: Y; Cap_F: 33nF; IRMS_A: 462.257mA; AEC Category: Q200
C9 = CMP-0079607-1: CAP, CERM, 1 µF, 16 V,+/- 10%, X7R, AEC-Q200 Grade 1, 0603; Manufacturer: TDK; TaMin_C: -55°C; Polarized: N; SizeAreaWB_mm2: 4.68; U/M: EA; Value: 1uF; TaMax_C: 125°C; SizeZ_mm: 1; SizeX_mm: 1.6; SizeY_mm: 0.8; Cap_Case: 0603; SizeArea_mm2: 1.28; AEC Qualified: Y; AEC Category: Q200
C10 = CMP-0007284-4: CAP, CERM, 82 pF, 100 V, +/- 5%, C0G/NP0, 0603; Manufacturer: MuRata; TaMin_C: -55°C; Polarized: N; SizeAreaWB_mm2: 4.68; U/M: EA; Value: 82pF; TaMax_C: 125°C; SizeZ_mm: 1; SizeX_mm: 1.6; SizeY_mm: 0.8; SizeArea_mm2: 1.28; AEC Category: Q200; Value1: Unknown
C11 = CMP-0007082-4: CAP, CERM, 0.01 uF, 100 V, +/- 10%, X7R, AEC-Q200 Grade 1, 0603; Manufacturer: TDK; TaMin_C: -55°C; ESR_ohm: 0.2354; Polarized: N; SizeAreaWB_mm2: 4.68; Value1: 0.235428 ohm; U/M: EA; Value: 0.01uF; TaMax_C: 125°C; SizeZ_mm: 1; SizeX_mm: 1.6; SizeY_mm: 0.8; SizeArea_mm2: 1.28; AEC Qualified: Y; Cap_F: 10nF; IRMS_A: 396.995mA; AEC Category: Q200
C12 C13 = CMP-0079095-1: CAP, CERM, 0.1 µF, 50 V,+/- 10%, X7R, AEC-Q200 Grade 1, 0603; Manufacturer: AVX; SizeAreaWB_mm2: 4.68; SizeArea_mm2: 1.28; AEC Qualified: Y; AEC Category: Q200; Value: 0.1uF; TaMax_C: 125°C; SizeZ_mm: 1; Polarized: N; TaMin_C: -55°C; VDC_V: 50V; SizeY_mm: 0.8; U/M: EA; SizeX_mm: 1.6; Cap_Case: 0603; ValueDisplayed: 0.1µF
C14 C15 C123-C128 = CMP-0084679-1: CAP, CERM, 0.1 µF, 25 V,+/- 10%, X7R, AEC-Q200 Grade 1, 0603; Manufacturer: MuRata; TaMin_C: -55°C; Polarized: N; SizeAreaWB_mm2: 4.68; U/M: EA; Value: 0.1uF; TaMax_C: 125°C; SizeZ_mm: 1; SizeX_mm: 1.6; SizeY_mm: 0.8; Value2: 25V; SizeArea_mm2: 1.28; AEC Qualified: Y; Cap_F: 100nF; AEC Category: Q200
C16 = CMP-0081783-1: CAP, CERM, 22 µF, 16 V,+/- 10%, X7R, 1210; Manufacturer: Samsung; TaMin_C: -55°C; Polarized: N; SizeAreaWB_mm2: 14.7; U/M: EA; Value: 22uF; TaMax_C: 125°C; SizeZ_mm: 2.7; SizeX_mm: 3.2; SizeY_mm: 2.5; Cap_Case: 1210; SizeArea_mm2: 8; AEC Category: Q200
C17 C23 C30 C32 = CMP-0008687-2: CAP, CERM, 10 uF, 10 V, +/- 10%, X7R, 1206; Manufacturer: TDK; TaMin_C: -55°C; ESR_ohm: 2.454m; Polarized: N; SizeAreaWB_mm2: 10.92; Value1: 0.002454 ohm; U/M: EA; Value: 10uF; TaMax_C: 125°C; SizeZ_mm: 1.35; SizeX_mm: 3.2; SizeY_mm: 1.6; SizeArea_mm2: 5.12; Cap_F: 10µF; IRMS_A: 4.6318A; AEC Category: Q200
C18 C25 = CMP-0083705-1: CAP, CERM, 1 µF, 50 V,+/- 10%, X7R, AEC-Q200 Grade 1, 0805; Manufacturer: AVX; TaMin_C: -55°C; Polarized: N; SizeAreaWB_mm2: 6.75; U/M: EA; Value: 1uF; TaMax_C: 125°C; SizeZ_mm: 1.45; SizeX_mm: 2; SizeY_mm: 1.25; Cap_Case: 0805; Value2: 50V; SizeArea_mm2: 2.5; AEC Qualified: Y; AEC Grade: 1; AEC Category: Q200
C19 C26 = CMP-0007977-2: CAP, CERM, 2.2 uF, 50 V, +/- 10%, X7R, AEC-Q200 Grade 1, 0805; Manufacturer: TDK; TaMin_C: -55°C; Polarized: N; SizeAreaWB_mm2: 6.75; Value1: 0.003288 ohm; U/M: EA; Value: 2.2uF; TaMax_C: 125°C; SizeZ_mm: 1.45; SizeX_mm: 2; SizeY_mm: 1.25; Cap_Case: 0805; Value2: 50V; SizeArea_mm2: 2.5; AEC Qualified: Y; Cap_F: 2.2µF; AEC Grade: 1; AEC Category: Q200; ESR_ohm: 3.288m; IRMS_A: 3.6003A
C20 C21 C24 C27 C28 C31 = CMP-0083705-1: CAP, CERM, 1 µF, 50 V,+/- 10%, X7R, AEC-Q200 Grade 1, 0805; Manufacturer: AVX; SizeAreaWB_mm2: 6.75; SizeArea_mm2: 2.5; AEC Qualified: Y; AEC Category: Q200; Value: 1uF; TaMax_C: 125°C; SizeZ_mm: 1.45; AEC Grade: 1; Polarized: N; TaMin_C: -55°C; VDC_V: 50V; SizeY_mm: 1.25; U/M: EA; CompType: Capacitor; SizeX_mm: 2; Cap_Case: 0805
C33-C36 = CMP-0007690-2: CAP, CERM, 4.7 uF, 10 V, +/- 10%, X7R, 0805; Manufacturer: Wurth Elektronik; TaMin_C: -55°C; Polarized: N; SizeAreaWB_mm2: 6.75; Value1: Unknown; U/M: EA; Value: 4.7uF; TaMax_C: 125°C; SizeZ_mm: 1.45; SizeX_mm: 2; SizeY_mm: 1.25; Cap_Case: 0805; SizeArea_mm2: 2.5; AEC Category: Q200
C37-C39 = CMP-0008317-2: CAP, CERM, 2.2 uF, 10 V, +/- 10%, X7R, 0805; Manufacturer: MuRata; TaMin_C: -55°C; ESR_ohm: 6m; Polarized: N; SizeAreaWB_mm2: 6.75; Value1: 0.006 ohm; U/M: EA; Value: 2.2uF; TaMax_C: 125°C; SizeZ_mm: 1.45; SizeX_mm: 2; SizeY_mm: 1.25; Cap_Case: 0805; SizeArea_mm2: 2.5; AEC Category: Q200
C40-C50 C76 C90-C109 = CMP-0012619-3: CAP, Tantalum Polymer, 1500 uF, 2.5 V, +/- 20%, 0.015 ohm, 7343-40 SMD; Manufacturer: Panasonic; TaMin_C: -55°C; ESR_ohm: 15m; Polarized: Y; SizeAreaWB_mm2: 58.59; Value: 1500uF; TaMax_C: 105°C; SizeZ_mm: 4; SizeX_mm: 7.3; SizeY_mm: 4.3; Cap_Case: D4; SizeArea_mm2: 31.39; CompType: Capacitor; AEC Qualified: N; Cap_F: 1.5mF; IRMS_A: 3.9A; AEC Category: Q200
C51-C54 C65 C77 = CMP-0079630-1: CAP, CERM, 1 µF, 16 V,+/- 10%, X7R, AEC-Q200 Grade 1, 0805; Manufacturer: Kemet; TaMin_C: -55°C; Polarized: N; SizeAreaWB_mm2: 6.75; U/M: EA; Value: 1uF; TaMax_C: 125°C; SizeZ_mm: 1.45; SizeX_mm: 2; SizeY_mm: 1.25; Cap_Case: 0805; SizeArea_mm2: 2.5; AEC Qualified: Y; AEC Grade: 1; AEC Category: Q200
C55 C57 C58 C61-C63 = CMP-0006724-5: CAP, CERM, 1000 pF, 100 V, +/- 10%, X7R, 0603; Manufacturer: AVX; TaMin_C: -55°C; Polarized: N; SizeAreaWB_mm2: 4.68; Value1: 0.276 ohm; U/M: EA; Value: 1000pF; TaMax_C: 125°C; SizeZ_mm: 1; SizeX_mm: 1.6; SizeY_mm: 0.8; Value2: 100V; SizeArea_mm2: 1.28; Cap_F: 1nF; AEC Category: Q200; ESR_ohm: 0.276
C56 C59 C60 C64 = CMP-0008483-2: CAP, CERM, 1000 pF, 100 V, +/- 10%, X7R, 1206; Manufacturer: AVX; TaMin_C: -55°C; Polarized: N; SizeAreaWB_mm2: 10.92; Value1: 0.427 ohm; U/M: EA; Value: 1000pF; TaMax_C: 125°C; SizeZ_mm: 1.35; SizeX_mm: 3.2; SizeY_mm: 1.6; Value2: 100V; SizeArea_mm2: 5.12; Cap_F: 1nF; AEC Category: Q200; ESR_ohm: 0.427
C66-C75 = CMP-0095928-1: 220 µF Molded Tantalum Polymer Capacitor 16 V 2917 (7343 Metric) 40mOhm @ 100kHz; Manufacturer: Kemet; Dissipation Factor: 10%; IRMS_A: 2.598A; Cap_F: 220µF; Standoff Height: 0mm; Value: 220µF; Esr: 40m; AEC Qualified: No; Life: 2000Hours; SizeZ_mm: 4.3mm; Tolerance_%: 20%; Leakage Current: 352uA
C78 C83 = CMP-0008483-2: CAP, CERM, 1000 pF, 100 V, +/- 10%, X7R, 1206; Manufacturer: AVX; TaMin_C: -55°C; Polarized: N; SizeAreaWB_mm2: 10.92; Value1: 0.427 ohm; U/M: EA; Value: 1000pF; TaMax_C: 125°C; SizeZ_mm: 1.35; SizeX_mm: 3.2; SizeY_mm: 1.6; Cap_Case: 1206; Value2: 100V; SizeArea_mm2: 5.12; Cap_F: 1nF; AEC Category: Q200; ESR_ohm: 0.427
C79 C80 C84 C85 = CMP-0008583-2: CAP, CERM, 0.01 uF, 250 V, +/- 10%, X7R, 1206; Manufacturer: Kemet; TaMin_C: -55°C; Polarized: N; SizeAreaWB_mm2: 10.92; Value1: Unknown; U/M: EA; Value: 0.01uF; TaMax_C: 125°C; SizeZ_mm: 1.35; SizeX_mm: 3.2; SizeY_mm: 1.6; Cap_Case: 1206; Value2: 250V; SizeArea_mm2: 5.12; Cap_F: 10nF; AEC Category: Q200
C81 C82 C86 C87 = CMP-0008973-2: CAP, CERM, 0.1 uF, 250 V, +/- 10%, X7R, 1206; Manufacturer: MuRata; TaMin_C: -55°C; Polarized: N; SizeAreaWB_mm2: 10.92; Value1: Unknown; U/M: EA; Value: 0.1uF; TaMax_C: 125°C; SizeZ_mm: 1.8; SizeX_mm: 3.2; SizeY_mm: 1.6; Cap_Case: 1206; Value2: 250V; SizeArea_mm2: 5.12; CompType: Capacitor; Cap_F: 100nF; AEC Category: Q200
C88 C112-C116 = CMP-0006946-4: CAP, CERM, 0.47 uF, 10 V, +/- 10%, X7R, 0603; Manufacturer: Kemet; TaMin_C: -55°C; Polarized: N; SizeAreaWB_mm2: 4.68; Value1: Unknown; U/M: EA; Value: 0.47uF; TaMax_C: 125°C; SizeZ_mm: 1; SizeX_mm: 1.6; SizeY_mm: 0.8; SizeArea_mm2: 1.28; AEC Category: Q200
C89 = CMP-0007601-2: CAP, CERM, 2200 pF, 50 V, +/- 5%, C0G/NP0, 0805; Manufacturer: AVX; SizeAreaWB_mm2: 6.75; SizeArea_mm2: 2.5; AEC Qualified: N; AEC Category: Q200; Value: 2200pF; TaMax_C: 125°C; SizeZ_mm: 1.45; TaMin_C: -55°C; SizeY_mm: 1.25; U/M: EA; SizeX_mm: 2; Cap_Case: 0805; ESR_ohm: 80m; Value1: 0.08 ohm
C110 C111 = CMP-0006814-5: CAP, CERM, 0.01 uF, 10 V, +/- 10%, X7R, 0603; Manufacturer: AVX; TaMin_C: -55°C; Polarized: N; SizeAreaWB_mm2: 4.68; U/M: EA; Value: 0.01uF; TaMax_C: 125°C; SizeZ_mm: 1; SizeX_mm: 1.6; SizeY_mm: 0.8; Value2: 10V; SizeArea_mm2: 1.28; AEC Category: Q200; Value1: Unknown
C117-C122 = CMP-0064931-4: CAP, CERM, 0.1 uF, 10 V,+/- 10%, X7R, 0603; Manufacturer: Wurth Elektronik; TaMin_C: -55°C; Polarized: N; SizeAreaWB_mm2: 4.68; Value1: Unknown; U/M: EA; Value: 0.1uF; TaMax_C: 125°C; SizeZ_mm: 1; SizeX_mm: 1.6; SizeY_mm: 0.8; SizeArea_mm2: 1.28; AEC Category: Q200
D1 = CMP-0076963-2: Diode, Superfast Rectifier, 50 V, 3 A, SMB; Manufacturer: Diodes Inc.; SizeZ_mm: 2.6; Vf_V: 900mV; TJmax_C: 150°C; Value1: 3A; Green_REACh: Incomplete; SizeY_mm: 3.81; AEC Category: Q101; SizeAreaWB_mm2: 44.156; SizeX_mm: 5.6; SizeArea_mm2: 21.336; Value2: 0.9V; Vr_V: 50V; Green_Lifecycle: Not Set; Value: 50V; RJC_CperW: 10.0
D2 D6 = CMP-0124121-1: Diode Zener Single 13V 500mW 2-Pin SOD-123 T/R; Manufacturer: Vishay; AEC Qualified: No; SizeZ_mm: 1.35mm; Power_W: 300mW; TJmax_C: 150°C; Vf_V: 13.26V; Vr_V: 10V; Max Reverse Leakage Current: 0.1uA; Zener Impedance: 25Ω
D5 = CMP-0076963-2: Diode, Superfast Rectifier, 50 V, 3 A, SMB; Manufacturer: Diodes Inc.; SizeZ_mm: 2.6; Vf_V: 900mV; Value1: 3A; Green_REACh: Incomplete; SizeY_mm: 3.81; AEC Category: Q101; TJmax_C: 150°C; SizeAreaWB_mm2: 44.156; SizeX_mm: 5.6; SizeArea_mm2: 21.336; Value2: 0.9V; Vr_V: 50V; Green_Lifecycle: Not Set; Value: 50V; RJC_CperW: 10.0
D7 D8 = CMP-0090591-1: Diode Schottky 40V 3A Surface Mount SMA; PartNumber: NRVBA340T3G; Manufacturer: ON Semiconductor; AEC Qualified: Yes; SizeZ_mm: 2.2mm; TJmax_C: 150°C; Peak Reverse Current: 0.3mA; Import Ts: 1521842727; Ciiva Ids: 822566; Max Surge Forward Current: 100A; AEC Grade: Grade 0; Standoff Height: 0.05mm
GND1-GND5 = CMP-0055138-2: Test Point, Miniature, Black, TH; Manufacturer: Keystone Electronics; CNHeader: FALSE; Green_Lifecycle: Active; Green_REACh: Passed; ContactFinish: Silver; CT: TRUE
J1 J2 J4 J5 = CMP-0055433-1: Compact Probe Tip Circuit Board Test Points, TH, 25 per; Manufacturer: Tektronix; PartNumber: 131-5031-00; CNHeader: FALSE; Green_Lifecycle: Not Set; Green_REACh: Incomplete
J3 = CMP-0055850-1: JACK, SMA, 50 Ohm, Gold, R/A, TH; Manufacturer: Linx Technologies; CNHeader: FALSE; CT: TRUE; Gender: Female
L1 L2 = CMP-0090776-1: Shielded Power Inductors - XAL1010 0.45uH AEC Q-200 20% 0.72mohm SRF: 66MHz 40A; Manufacturer: Coilcraft; Isat: 70.5A; Irms: 53A; DCR_ohm: 720µ; Material: Composite; SizeZ_mm: 10mm; Ind_H: 450nH; AEC Qualified: Yes; AEC Grade: Grade 1; TaMin_C: -40°C; TaMax_C: +125°C; Test Frequency: 1MHz; Shrouded: true
Q1 Q3 Q4 Q6-Q10 = CMP-0044865-1: MOSFET N-Channel 40 V 80A (Tc) Surface Mount 5-SMD; Manufacturer: EPC Space; AEC Qualified: No; QgTyp_nC: 22nC @ 0V; Rdson45_ohm: 3.7m; SizeZ_mm: 2.235mm; VdsMax_V: 40V; Vgs_V: 6V; ChMode: False; Input Capacitace At Vds: 2830pF @ 20V; Number Of Channels: 1; Pulse Drain Current: 530A; Rthja Max: 48°C/W; Threshold Vgs Max: 2.5V; Threshold Vgs Min: 0.8V; TJmax_C: +150°C
Q11 = CMP-0000264-1: MOSFET, N-CH, 25 V, 113 A, DQH0008A (VSON-CLIP-8); Alternate Manufacturer: None; Manufacturer: Texas Instruments; SizeZ_mm: 1.05; ChType: N; Value2: 6.7 nC; Value1: 0.005; VdsMax_V: 25V; SizeX_mm: 6; SizeY_mm: 5; Vgs_V: 16V; Value: 25V; Rdson45_ohm: 5.4m; SizeArea_mm2: 30; AEC Category: Q101; IdsMax_A: 113A; SizeAreaWB_mm2: 56; U/M: EA; QgTyp_nC: 6.7
R1 R5 R12 R14 R18 R24 R46 R71 R74-R79 R84 R87-R92 = CMP-0023343-3: RES, 0, 1%, 0.1 W, AEC-Q200 Grade 0, 0603; Manufacturer: Stackpole Electronics Inc; Power_W: 100mW; TempCo: ppm/C; U/M: EA; Value: 0; SizeX_mm: 1.6; SizeY_mm: 0.8; SizeZ_mm: 1; Value2: 0.1W; SizeArea_mm2: 1.28; AEC Qualified: Y; AEC Category: Q200
R2 = CMP-0023142-5: RES, 49.9 k, 1%, 0.1 W, 0603; Manufacturer: Yageo; Power_W: 100mW; TempCo: 100 ppm/C; Value_Code: 49k9; Value: 49.9k; EIA_Code: E96; SizeX_mm: 1.6; SizeY_mm: 0.8; SizeZ_mm: 1; Value2: 0.1W; SizeArea_mm2: 1.28; AEC Qualified: N; VDC_V: 75V; AEC Category: Q200; SizeAreaWB_mm2: 4.68
R3 = CMP-0022751-4: RES, 10.0, 1%, 0.1 W, 0603; Manufacturer: Yageo; Power_W: 100mW; TempCo: 100 ppm/C; Value_Code: 10R0; Value: 10.0; EIA_Code: E96; Res_ohm: 10; SizeX_mm: 1.6; SizeY_mm: 0.8; SizeZ_mm: 1; Value2: 0.1W; SizeArea_mm2: 1.28; AEC Qualified: N; VDC_V: 75V; AEC Category: Q200; SizeAreaWB_mm2: 4.68
R4 = CMP-0023143-5: RES, 49.9, 1%, 0.1 W, 0603; Manufacturer: Yageo; Power_W: 100mW; TempCo: 100 ppm/C; SizeAreaWB_mm2: 4.68; Value_Code: 49R9; Value: 49.9; EIA_Code: E96; SizeX_mm: 1.6; SizeY_mm: 0.8; SizeZ_mm: 1; Value2: 0.1W; SizeArea_mm2: 1.28; AEC Qualified: N; AEC Category: Q200; VDC_V: 75V
R6 = CMP-0023077-5: RES, 3.09 k, 1%, 0.1 W, 0603; Manufacturer: Yageo; Power_W: 100mW; TempCo: 100 ppm/C; Value_Code: 3k09; Value: 3.09k; EIA_Code: E96; SizeX_mm: 1.6; SizeY_mm: 0.8; SizeZ_mm: 1; Value2: 0.1W; SizeArea_mm2: 1.28; AEC Qualified: N; VDC_V: 75V; AEC Category: Q200; SizeAreaWB_mm2: 4.68
R7 = CMP-0023404-3: RES, 10.0 k, 0.1%, 0.1 W, 0603; Manufacturer: Susumu Co Ltd; Power_W: 100mW; TempCo: 25 ppm/C; Value_Code: 10k0; U/M: EA; Value: 10.0k; EIA_Code: E192; Res_ohm: 10k; SizeX_mm: 1.6; SizeY_mm: 0.8; SizeZ_mm: 1; Value2: 0.1W; SizeArea_mm2: 1.28; VDC_V: 75V; AEC Category: Q200
R8 = CMP-0023070-4: RES, 392 k, 1%, 0.1 W, 0603; Manufacturer: Yageo; Power_W: 100mW; TempCo: 100 ppm/C; Value: 392k; EIA_Code: E96; SizeX_mm: 1.6; SizeY_mm: 0.8; SizeZ_mm: 1; Value2: 0.1W; SizeArea_mm2: 1.28; AEC Qualified: N; VDC_V: 75V; AEC Category: Q200; SizeAreaWB_mm2: 4.68
R9 = CMP-0022098-4: RES, 18.7 k, 1%, 0.1 W, AEC-Q200 Grade 0, 0603; Manufacturer: Vishay-Dale; Power_W: 100mW; TempCo: 100 ppm/C; Value_Code: 18k7; Value: 18.7k; EIA_Code: E96; SizeX_mm: 1.6; SizeY_mm: 0.8; SizeZ_mm: 1; Value2: 0.1W; SizeArea_mm2: 1.28; AEC Qualified: Y; VDC_V: 75V; AEC Category: Q200; AEC Grade: 0
R10 = CMP-0023517-2: RES, 33.2 k, 0.1%, 0.1 W, 0603; Manufacturer: Susumu Co Ltd; Power_W: 100mW; TempCo: 25 ppm/C; Value_Code: 33k2; U/M: EA; Value: 33.2k; EIA_Code: E192; SizeX_mm: 1.6; SizeY_mm: 0.8; SizeZ_mm: 1; Value2: 0.1W; SizeArea_mm2: 1.28; VDC_V: 75V; AEC Category: Q200
R11 R13 = CMP-0025332-2: RES, 49.9 k, 0.5%, 0.1 W, 0603; Manufacturer: Yageo America; Power_W: 100mW; TempCo: 50 ppm/C; Value_Code: 49k9; U/M: EA; Value: 49.9k; EIA_Code: E192; SizeX_mm: 1.6; SizeY_mm: 0.8; SizeZ_mm: 1; Value2: 0.1W; SizeArea_mm2: 1.28; VDC_V: 75V; AEC Category: Q200
R15 R16 R19 R20 = CMP-0020063-2: RES, 41.2 k, 0.1%, 0.125 W, 0805; Manufacturer: Yageo America; Power_W: 125mW; TempCo: 25 ppm/C; Value_Code: 41k2; U/M: EA; Value: 41.2k; EIA_Code: E192; SizeX_mm: 2; SizeY_mm: 1.25; SizeZ_mm: 1.45; Value2: 0.125W; SizeArea_mm2: 2.5; VDC_V: 150V; AEC Category: Q200
R17 R21 = CMP-0023899-3: RES, 1.50 k, 0.1%, 0.1 W, 0603; Manufacturer: Yageo America; Power_W: 100mW; TempCo: 25 ppm/C; Value_Code: 1k50; U/M: EA; Value: 1.50k; EIA_Code: E192; Res_ohm: 1.5k; SizeX_mm: 1.6; SizeY_mm: 0.8; SizeZ_mm: 1; Value2: 0.1W; SizeArea_mm2: 1.28; VDC_V: 75V; AEC Category: Q200
R23 R45 = CMP-0096593-1: 2 Ohms ±1% 0.25W, 1/4W Chip Resistor 0603 (1608 Metric) Automotive AEC-Q200, Pulse Withstanding Thick Film; Manufacturer: Vishay Dale; Power_W: 250mW; TempCo: 100ppm/°C; SizeZ_mm: 0.55mm; AEC Qualified: Yes; VDC_V: 75V; AEC Grade: Grade 0
R28-R33 = CMP-0015108-2: RES, 0.007, 1%, 3 W, 2512 WIDE; Manufacturer: Susumu Co Ltd; Res_ohm: 7m; TempCo: 50 ppm/C; SizeZ_mm: 0.7; Power_W: 3W; SizeAreaWB_mm2: 43.16; Value_Code: 7L000; U/M: EA; EIA_Code: E96; SizeX_mm: 3.2; SizeY_mm: 6.3; SizeArea_mm2: 20.16; AEC Category: Q200
R67 = CMP-0024533-3: RES, 931, 0.1%, 0.1 W, 0603; Manufacturer: Yageo America; Power_W: 100mW; TempCo: 25 ppm/C; Value_Code: 931R; U/M: EA; Value: 931; EIA_Code: E192; SizeX_mm: 1.6; SizeY_mm: 0.8; SizeZ_mm: 1; Value2: 0.1W; SizeArea_mm2: 1.28; VDC_V: 75V; AEC Category: Q200
R68 R69 R81 R82 = CMP-0023337-3: RES, 10.0 k, 1%, 0.1 W, 0603; Manufacturer: Vishay Draloric; Power_W: 100mW; TempCo: 100 ppm/C; Value_Code: 10k0; U/M: EA; Value: 10.0k; Res_ohm: 10k; SizeX_mm: 1.6; SizeY_mm: 0.8; SizeZ_mm: 1; Value2: 0.1W; SizeArea_mm2: 1.28; AEC Qualified: N; AEC Category: Q200; EIA_Code: E96; VDC_V: 75V
R70 R83 = CMP-0025804-4: RES, 3.0, 5%, 0.1 W, AEC-Q200 Grade 0, 0603; Manufacturer: Vishay-Dale; Power_W: 100mW; TempCo: 200 ppm/C; Value_Code: 3R00; Value: 3.0; Res_ohm: 3; SizeX_mm: 1.6; SizeY_mm: 0.8; SizeZ_mm: 1; Value2: 0.1W; SizeArea_mm2: 1.28; AEC Qualified: Y; AEC Category: Q200; AEC Grade: 0; EIA_Code: E24; VDC_V: 75V
R94 = CMP-0081973-1: RES, 0, 0%, 0.25 W, AEC-Q200 Grade 0, 0603; Manufacturer: Vishay-Dale; SizeAreaWB_mm2: 4.68; SizeArea_mm2: 1.28; AEC Qualified: Y; AEC Category: Q200; Value: 0; SizeZ_mm: 1; SizeY_mm: 0.8; Power_W: 250mW; Value2: 0.25W; SizeX_mm: 1.6
R95 = CMP-0023392-3: RES, 10.0 k, 0.1%, 0.0375 W, 0603; Manufacturer: Vishay Sfernice; Power_W: 37.5mW; TempCo: 15 ppm/C; Value_Code: 10k0; U/M: EA; Value: 10.0k; EIA_Code: E192; Res_ohm: 10k; SizeX_mm: 1.6; SizeY_mm: 0.8; SizeZ_mm: 1; SizeArea_mm2: 1.28; VDC_V: 75V; AEC Category: Q200
R96 R97 = CMP-0015854-2: RES, 0.04, 1%, 2 W, AEC-Q200 Grade 0, 2512; Manufacturer: Vishay-Dale; Power_W: 2W; TempCo: 75 ppm/C; Value_Code: R040; U/M: EA; Value: 0.04; Res_ohm: 40m; SizeX_mm: 6.3; SizeY_mm: 3.2; SizeZ_mm: 0.71; SizeArea_mm2: 20.16; AEC Qualified: Y; AEC Grade: 0; AEC Category: Q200
R99 = CMP-0022899-4: RES, 1.00 M, 1%, 0.1 W, 0603; Manufacturer: Yageo; Power_W: 100mW; TempCo: 100 ppm/C; Value_Code: 1M00; Value: 1.00Meg; EIA_Code: E96; Res_ohm: 1M; SizeX_mm: 1.6; SizeY_mm: 0.8; SizeZ_mm: 1; Value2: 0.1W; SizeArea_mm2: 1.28; AEC Qualified: N; VDC_V: 75V; AEC Category: Q200; SizeAreaWB_mm2: 4.68
R100 R101 = CMP-0123586-1: 500 mOhms ±1% 4W Chip Resistor 2512 (6432 Metric) Automotive AEC-Q200, Current Sense, Moisture Resistant, Pulse Withstanding Metal Foil; Manufacturer: Isabellenhuette; TempCo: 20ppm/°C; Value: 0.5; SizeZ_mm: 0.55mm; AEC Qualified: Yes; AEC Grade: Grade 0
TP3-TP5 = CMP-0055139-1: Test Point, Miniature, White, TH; Manufacturer: Keystone; CNHeader: FALSE; Green_Lifecycle: Active; Green_REACh: Passed; ContactFinish: Silver; CT: TRUE
TP7 TP8 TP10 = CMP-0055137-2: Test Point, Miniature, Red, TH; Manufacturer: Keystone Electronics; CNHeader: FALSE; Green_Lifecycle: Active; Green_REACh: Passed; ContactFinish: Silver; CT: TRUE
TP13 = CMP-0055152-2: Test Point, Miniature, SMT; Manufacturer: Keystone Electronics; CT: TRUE; Green_Lifecycle: Active; Green_REACh: Passed; CNHeader: FALSE
U1 = CMP-0094374-1: Radiation-Hardness-Assured Current Mode PWM Controllers; Manufacturer: Texas Instruments; AEC Qualified: No; Output Type: AdjustableProgrammable; Max Supply Voltage: 14V; Number Of Outputs: 2; Switching Frequency: 100-2000kHz; TJmax_C: +125°C; Nominal Supply Current: 6.25-14mA; Min Supply Voltage: 4V; SizeZ_mm: 2.428mm; Max Duty Cycle: 50%; Switching Topology: Buck,Push-Pull,Other
U3 U4 = CMP-0096403-3: Radiation-Hardness-Assured 200-V, 1.5-A 3-A, Half Bridge GaN FET Gate Driver; Part Number: TPS7H6003/EM; Manufacturer: Texas Instruments; CompType: IC; Turn Off Delay Time: 25ns; Fall Time: 3ns; Number Of Drivers: 2; Rise Time: 5ns; TJmax_C: +125°C; Max Supply Voltage: 14V; AEC Qualified: No; AEC Category: Q200; SizeZ_mm: 2.667mm; Min Supply Voltage: 10V; Standoff Height: 0mm
Vin = CMP-0078537-1: Fixed Terminal Blocks MKDSP 10 HV/ 2-10; Manufacturer: Phoenix Contact; PartNumber: 1929517; Voltage_V: 1kV; Current_A: 76A; Row_Count: 1

## Sheet Hardware.SchDoc
size 431 x 279 mm; Date: Not shown in title block; ApprovedBy: Not shown in title block; CheckedBy: Not shown in title block; Author: Not shown in title block; CompanyName: Not shown in title block; Engineer: Not shown in title block; Organization: Not shown in title block; Address1: Not shown in title block; Address2: Not shown in title block; Address3: Not shown in title block; Address4: Not shown in title block; DocumentNumber: 1; Revision: Use project parameter SCH_Rev; SheetNumber: 2; SheetTotal: 2; PageSetup: Record=PageOptions¦CenterHorizontal=True¦CenterVertical=True¦PrintScale=1.00¦XCorrection=1.00¦YCorrection=1.00¦PrintKind=0¦BorderSize=5000000¦LeftOffset=0¦BottomOffset=0¦Orientation=2¦PaperLength=1000¦PaperWidth=1000¦Scale=100¦PaperSource=15¦PrintQuality=600¦MediaType=1¦DitherType=10¦PaperKind=Letter¦PrintScaleMode=1
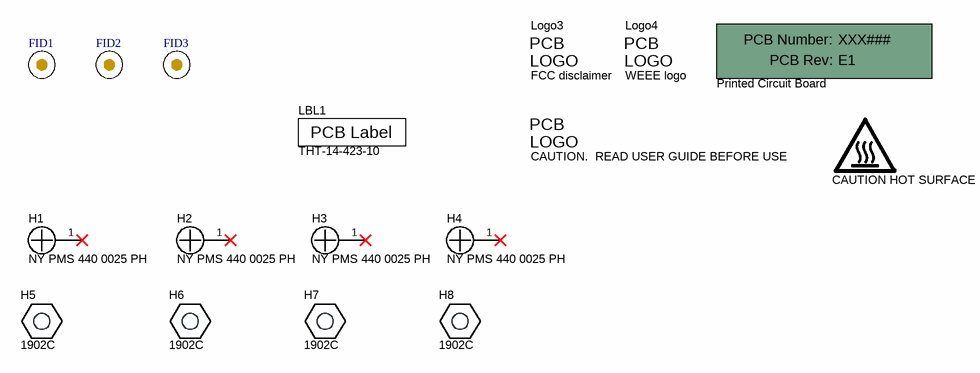
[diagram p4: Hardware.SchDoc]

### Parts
!PCB  Printed Circuit Board  (mechanical)
FID1  Fiducial  [Fiducial10-20]  (value not drawn)
FID2  Fiducial  [Fiducial10-20]  (value not drawn)
FID3  Fiducial  [Fiducial10-20]  (value not drawn)
H1  NY PMS 440 0025 PH  [NY PMS 440 0025 PH]
H2  NY PMS 440 0025 PH  [NY PMS 440 0025 PH]
H3  NY PMS 440 0025 PH  [NY PMS 440 0025 PH]
H4  NY PMS 440 0025 PH  [NY PMS 440 0025 PH]
H5  1902C  [Keystone_1902C]
H6  1902C  [Keystone_1902C]
H7  1902C  [Keystone_1902C]
H8  1902C  [Keystone_1902C]
LBL1  THT-14-423-10  [Label_650x200]
Logo1  CAUTION HOT SURFACE  [IEC_HotSurface_Small]  (no BOM)
Logo3  FCC disclaimer  [FCC_disclaimer_stacked]  (no BOM)
Logo4  WEEE logo  [WEEE_Minimum]  (no BOM)
Logo5  CAUTION.  READ USER GUIDE BEFORE USE  [IEC_Caution_Small]  (no BOM)

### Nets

Not connected (* = marked no-connect by the designer): H1 1*; H2 1*; H3 1*; H4 1*

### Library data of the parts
!PCB = CMP-0003618-2: PartNumber: XXX###; Manufacturer: Any
FID1-FID3 = CMP-0077181-1: Fiducial mark.  There is nothing to buy or mount.
H1-H4 = CMP-0003617-1: Machine Screw, Round, #4-40 x 1/4, Nylon, Philips panhead; Manufacturer: B&F Fastener Supply; CompType: Hardware
H5-H8 = CMP-0003610-1: Standoff, Hex, 0.5"L #4-40 Nylon; Manufacturer: Keystone; CompType: Hardware
LBL1 = CMP-0003625-1: Manufacturer: Brady
Logo1 = CMP-0074837-2: IEC 61010-1 Hot Surface Warning; Manufacturer: Texas Instruments; CompType: IC; AEC Category: Q200; SymbolCreator: a0412235
Logo3 = CMP-0074847-1: FCC_disclaimer
Logo4 = CMP-0074769-3: Manufacturer: Texas Instruments; CompType: IC; AEC Category: Q200
Logo5 = CMP-0074836-1: IEC 61010-1 Caution Warning; Lib Reference: IEC_Caution; SymbolCreator: a0412235

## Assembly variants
001: not fitted C94 C95 C96 C97 C98 C99 C100 C101 C102 C103 C104 C105 C106 C107 C108 C109 C110 C111 FID1 FID2 FID3 R100 R101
